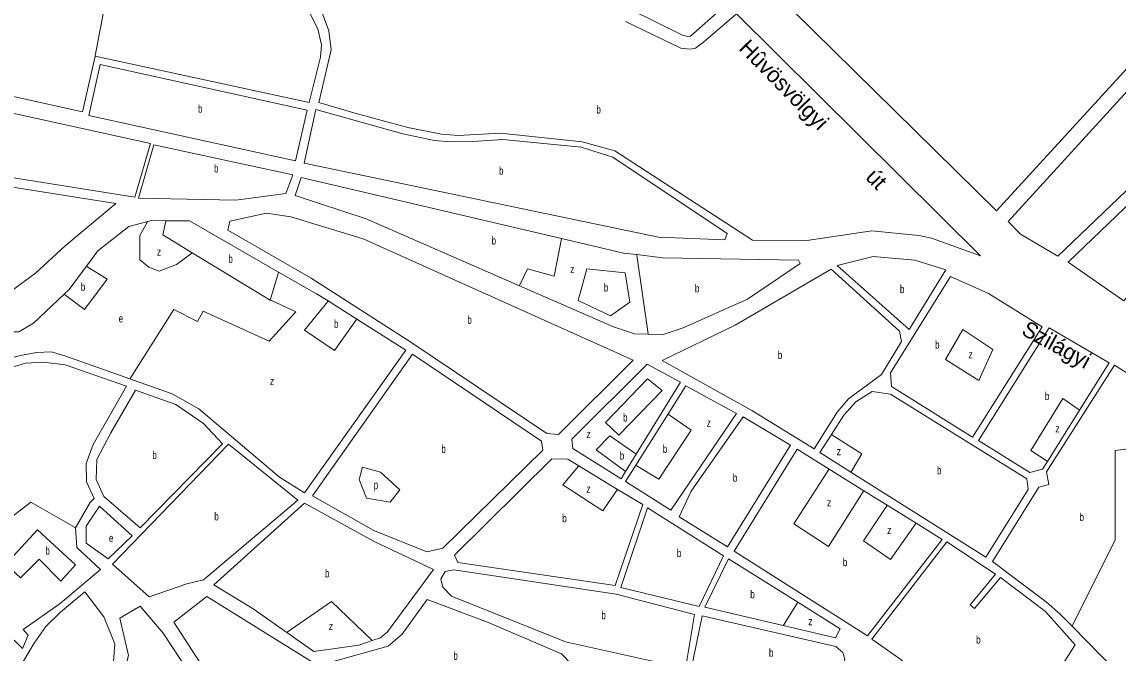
# Model space of a CAD drawing. Extents: x 639657 to 671642, y 222838 to 252123.
# Drawn here: x 644946 to 646316, y 241013 to 241801 of the extents above; entities that cross this region are included whole.
import ezdxf
from ezdxf.enums import TextEntityAlignment as Align

# ---------------------------------------------------------------- set-up
doc = ezdxf.new("R2010")
doc.units = 0
doc.header["$LTSCALE"] = 4
doc.layers.add('1', color=7, linetype='Continuous', lineweight=13)
doc.layers.add('21', color=7, linetype='Continuous', lineweight=13)
doc.layers.add('22', color=7, linetype='Continuous')
doc.layers.add('7', color=7, linetype='Continuous')

msp = doc.modelspace()

# ---------------------------------------------------------------- linework, layer by layer
at = {"layer": '1'}
for p, q in [((645294.9, 241607.15), (645620.206, 241530.732)), ((645004.92, 241467.24), (645026.293, 241496.041)), ((645942.86, 241263.31), (645957.318, 241285.861)), ((645828.86, 241130.7), (645915.416, 241076.328))]:
    msp.add_line(p, q, dxfattribs=at)
for points in [[(645858.47, 241865.89), (646093.56, 242109.01), (646187.78, 242031.94), (646214.33, 241999.51), (646251.88, 241958.28), (646371.69, 241821.18), (646376.66, 241813.26), (646376.91, 241804.46), (646374.59, 241796.51), (646367.97, 241788.32), (646163.68, 241565.33)], [(645623.52, 241961.51), (645494.3, 241854.3), (645497.53, 241851.96), (645507.65, 241846.42), (645520.12, 241842.82), (645705.57, 241817.4), (645771.43, 241784.83), (645777.88, 241782.92), (645781.32, 241783.58), (645824.74, 241821.75)], [(646178.34, 241551.87), (646402.29, 241797.05), (646433.14, 241765.19), (646467.24, 241725.61), (646240.37, 241508.54), (646193.44, 241536.26)], [(645106.26, 241649.4), (645086.89, 241582.34), (644817.41, 241625.16), (644745.05, 241620.53), (644683.4, 241628.38), (644656.74, 241641.65), (644628.6, 241649.55), (644601.96, 241651.44), (644539.47, 241650.27), (644554.95, 241770.56)], [(645043.37, 241748.13), (645302.41, 241691.25), (645287.45, 241627.66), (645029.27, 241684.33)], [(646253.29, 241501.08), (646475.02, 241714.05), (646508.76, 241660.31), (646322.64, 241452.84)], [(645298.63, 241624.7), (645313.15, 241691.73), (645421.73, 241661.48), (645461.29, 241653.27), (645480.84, 241651.63), (645509.4, 241651.75), (645546.54, 241654.48), (645644.51, 241644.79), (645684.07, 241632.5), (645826.88, 241536.92), (645824.12, 241529.18), (645741.43, 241532.5)], [(645110.79, 241647.97), (645284.17, 241610.39), (645275.74, 241586.8), (645213.24, 241578.58), (645091.3, 241581.24)], [(645709.56, 241378.97), (645616.36, 241286.02), (645601.55, 241287.34), (645431.58, 241401.34), (645307.04, 241481.09), (645203.27, 241541.25), (645205.66, 241552.62), (645251.2, 241562.38), (645281.68, 241558.01), (645372.21, 241530.52)], [(645964.48, 241497.07), (646009.38, 241508.12), (646061.76, 241503.69), (646100.37, 241491.58), (646054.67, 241416.97)], [(645956.96, 241492.36), (646042.43, 241414.86), (646044.76, 241402.18), (646019.75, 241361.02), (645978.89, 241330.42), (645964.46, 241313.93), (645935.58, 241268.05), (645857.76, 241315.91), (645745.63, 241378.45), (645837.2, 241422.67)], [(646106.15, 241483.19), (646153.55, 241462.25), (646220.64, 241420.43), (646133.57, 241282.81), (646032.6, 241345.75), (646031.35, 241362.93)], [(645433.88, 241386.28), (645595.03, 241277.47), (645596.72, 241266.3), (645471.7, 241144.04), (645451.94, 241139.59), (645385.67, 241166.16), (645308.72, 241209.5)], [(645775.61, 241346.82), (645838.64, 241312.31), (645756.76, 241191.42), (645700.17, 241227.2), (645712.987, 241247.523), (645753.099, 241311.125)], [(645196.23, 241274.37), (645093.58, 241169.2), (645048.13, 241208.53), (645038.6, 241229.75), (645039.57, 241254.87), (645057.05, 241288.22), (645087.54, 241341.37), (645138.07, 241323.32), (645172.51, 241299.83)], [(645847.01, 241308.21), (645906.39, 241272.63), (645827.5, 241145.73), (645767.04, 241183.02), (645781.94, 241214.97)], [(645290.576, 241203.955), (645203.75, 241273.97), (645058.97, 241124.19), (645104.65, 241083.36), (645151.82, 241099.43), (645172.55, 241104.39)], [(645042.543, 241196.564), (645083.53, 241159.5), (645053.37, 241130.61), (645025.92, 241150.06), (645026.24, 241171.35)], [(645727.49, 241194.49), (645822.43, 241134.58), (645792, 241071.11), (645694.18, 241094.97)], [(646101.68, 241151.7), (646162.34, 241111.62), (646130.68, 241073.05), (646136.26, 241068.53), (646168.77, 241107.31), (646224.92, 241064.66), (646261.96, 241023.13), (646180.92, 240897.73), (646142.33, 240922.31), (646093.48, 240961.5), (646044.21, 241004.78), (646007.77, 241030.42)], [(645786.4, 241061.25), (645775.07, 240993.66), (645624.89, 241026.88), (645482.71, 241083.91), (645471.57, 241095.1), (645469.24, 241105.62), (645474.84, 241114.84), (645485.58, 241116.75), (645688.15, 241086.61)], [(644991.7, 240939.28), (645008.1, 240899.42), (645042.03, 240953.01), (645059.49, 240991.08), (645061.72, 241024.37), (645048.06, 241058.24), (645024.33, 241089.28), (644993.95, 241063.95), (644975.56, 241045.99), (644961.2, 241025.13), (644946.85, 241001.48), (644975.69, 240965.66)], [(645308.72, 241001.71), (645177, 241083.64), (645135.47, 241051.49), (645185.8, 240973.75), (645205.97, 240922.94), (645226.87, 240903.49), (645242.77, 240900.76), (645270.69, 240952.4)], [(645251.66, 240876.75), (645141.82, 240854.42), (645034.32, 240838.33), (645015.47, 240881.41), (645067.96, 240967.28), (645078.95, 241010.05), (645068.25, 241056.38), (645093.53, 241071.73), (645122.43, 241037.7), (645168.22, 240968.31), (645187.94, 240921.37), (645205.64, 240896.96), (645231.24, 240884.18)], [(645664.14, 240929.33), (645644.75, 240986.48), (645619.91, 241012.08), (645527.7, 241051.38), (645452.21, 241079.69), (645420.98, 241036.62), (645403.34, 241021.43), (645329.01, 241000.79), (645369.31, 240976.43), (645396.12, 240967.78), (645423.59, 240965.78), (645486.28, 240969.7), (645599.81, 240959.33), (645626.2, 240952.82), (645648.93, 240941.17)], [(645795.62, 241059.51), (645962.97, 241021.31), (645971.75, 241013.56), (645974.09, 241005.18), (645971.27, 240995.32), (645948.85, 240957.38), (645782.15, 240992.57)]]:
    msp.add_lwpolyline(points, close=True, dxfattribs=at)
for points in [[(645037.09, 241758.62), (645304.73, 241700.49), (645318.86, 241757.43), (645320.08, 241772.88), (645315.48, 241792.61), (645306.16, 241811.25), (645292.56, 241826.86), (645270.59, 241840.72), (645127.41, 241918.46), (645135.72, 241933.95), (645116.95, 241950.82), (645084.37, 241996.49), (645078.639, 242000.453)], [(645700.06, 241801.71), (645769.14, 241768.72), (645780.32, 241767.26), (645787.4, 241768.58), (645797.46, 241776.13), (645838.53, 241811.5), (646143.74, 241509.01), (646082.44, 241531.09), (646066.75, 241534.67), (646007.89, 241540.45), (645926.77, 241528.1), (645858.91, 241528.9), (645686.83, 241640.24), (645645.98, 241651.67), (645543.71, 241662.41), (645490.89, 241659.4), (645470.05, 241661.25), (645428.14, 241669.45), (645360.41, 241687.63), (645316.76, 241700.54), (645332.13, 241766.28), (645329.45, 241790.09), (645320.53, 241814.09)], [(644576.8, 241787.77), (645021.54, 241689.2), (645037.09, 241758.62)], [(644708.734, 241612.95), (644744.64, 241608.5), (644835.91, 241610.37), (645062.99, 241574.55)], [(645567.455, 241471.564), (645375.92, 241555.2), (645287.33, 241584.41), (645294.9, 241607.15)], [(645062.99, 241574.55), (644999.49, 241521.29), (644962.82, 241487.3), (644908.55, 241448.13), (644832.57, 241416.86), (644705.42, 241424.17), (644533.43, 241398.98), (644486.42, 241386.24), (644467.47, 241417.35)], [(645026.293, 241496.041), (645040.51, 241515.2), (645079.44, 241545.8), (645102.976, 241551.985)], [(645102.976, 241551.985), (645107.79, 241553.25), (645125.865, 241553.04)], [(645125.865, 241553.04), (645155.23, 241552.7), (645266.6, 241488.903)], [(645620.206, 241530.732), (645697.65, 241512.54), (645714.032, 241510.624)], [(645714.032, 241510.624), (645746.37, 241506.84), (645916.19, 241503.63), (645918.12, 241499.54), (645852.52, 241455.05), (645772.14, 241419.18), (645747, 241410.87), (645728.363, 241411.361)], [(645266.6, 241488.903), (645314.07, 241461.71), (645328.331, 241452.72), (645364.287, 241430.052)], [(645080.793, 241355.346), (644999.28, 241384.27), (644982.52, 241389.4), (644963.84, 241388.51), (644943.87, 241384.61), (644914.24, 241377.26), (644901.36, 241377.24), (644887.39, 241384.09), (644876.63, 241396.53), (644910.96, 241414.2), (644942.1, 241414.25), (644960.13, 241425.02), (644998.619, 241461.301), (645004.92, 241467.24)], [(645728.363, 241411.361), (645711.36, 241411.81), (645684.97, 241420.25), (645567.455, 241471.564)], [(645364.287, 241430.052), (645425.52, 241391.45), (645298.85, 241213.17), (645267.56, 241232.78), (645166.67, 241317.83), (645133.65, 241336.59), (645080.793, 241355.346)], [(646227.269, 241252.227), (646221.28, 241242.66), (646205.38, 241238.62), (646141.07, 241278.49), (646229.44, 241419.33)], [(646229.44, 241419.33), (646304.48, 241375.56), (646267.492, 241316.477), (646227.269, 241252.227)], [(645012.85, 241169.32), (645030.98, 241200.95), (645036.11, 241206.12), (645026.58, 241226.91), (645026.07, 241249.67), (645034.78, 241273.32), (645076.36, 241346.26), (644999.73, 241373.11), (644972.88, 241376.29), (644950.11, 241374.96), (644922.64, 241366.54)], [(645700.112, 241239.636), (645694.59, 241230.65), (645634.14, 241268.37), (645633.1, 241279.97), (645726.94, 241373.77)], [(645726.94, 241373.77), (645768.75, 241351.34), (645713.404, 241261.268), (645700.112, 241239.636)], [(646258.097, 241046.403), (646243.37, 241061.39), (646226.23, 241076.68), (646158.73, 241127.3), (646216.5, 241220.34), (646228.96, 241223.31), (646226.21, 241239.42), (646310.91, 241372.76)], [(646310.91, 241372.76), (646361.51, 241341.07), (646456.485, 241240.94)], [(645957.318, 241285.861), (645972.82, 241310.04), (645987.68, 241326.75), (646008.11, 241339.58), (646031.29, 241336.31), (646201.71, 241230.68), (646203.39, 241217.15), (646150.37, 241132.91), (645981.524, 241239.014), (645942.86, 241263.31)], [(646063.12, 241175.164), (646095.68, 241154.94), (646002.63, 241034.51), (645835.86, 241140.34), (645914.53, 241267.46)], [(645914.53, 241267.46), (645954.501, 241242.632), (645997.793, 241215.742), (646027.097, 241197.54), (646063.12, 241175.164)], [(645690.119, 241217.352), (645721.48, 241198.37), (645687.31, 241097.14), (645490.33, 241125.97), (645486.49, 241135.42), (645607.86, 241255.54)], [(645607.86, 241255.54), (645627.82, 241255.06), (645641.523, 241246.766), (645690.119, 241217.352)], [(646456.485, 241240.94), (646531.75, 241161.59), (646404.34, 241038.24), (646398.72, 241021.51), (646410.23, 240990.35), (646389.8, 240976.87), (646373.86, 240954.37), (646336.33, 240973.35), (646311.47, 240992.09), (646258.097, 241046.403)], [(645276.805, 241038.585), (645234.73, 241068.22), (645185.43, 241097.97), (645298.82, 241200.29), (645386.07, 241152.2), (645460.04, 241117.24)], [(644993.68, 241074.72), (645043.76, 241117.48), (645014.45, 241144.85), (645012.85, 241169.32)], [(645897.041, 241047.441), (645799.09, 241070.45), (645828.86, 241130.7)], [(645460.04, 241117.24), (645402.53, 241039.46), (645393.92, 241032.18), (645383.641, 241028.649)], [(644876.758, 241081.749), (644904.23, 241059.4), (644946.611, 241018.583), (644953.45, 241035.21), (644947.22, 241042.29), (644993.68, 241074.72)], [(645915.416, 241076.328), (645968.17, 241043.19), (645962.56, 241032.05), (645897.041, 241047.441)], [(645383.641, 241028.649), (645366.64, 241022.81), (645310.59, 241014.79), (645276.805, 241038.585)]]:
    msp.add_lwpolyline(points, dxfattribs=at)
at = {"layer": '21'}
for points in [[(645053.824, 241945.481), (645033.777, 241900.353), (645060.507, 241881.967), (645037.185, 241759.12), (645037.09, 241758.62)], [(645158.643, 241513.001), (645158.143, 241512.626), (645138.804, 241498.114), (645117.475, 241489.986), (645104.272, 241495.066), (645093.1, 241504.211), (645093.1, 241534.694), (645102.69, 241551.485), (645102.976, 241551.985)], [(645158.643, 241513.001), (645122.043, 241535.193), (645125.758, 241552.54), (645125.865, 241553.04)], [(645567.455, 241471.564), (645567.69, 241472.064), (645577.554, 241493.034), (645611.07, 241483.889), (645620.108, 241530.232), (645620.206, 241530.732)], [(645266.6, 241488.903), (645266.45, 241488.403), (645256.105, 241453.905), (645158.643, 241513.001)], [(645728.363, 241411.361), (645728.291, 241411.862), (645714.104, 241510.123), (645714.032, 241510.624)], [(645026.293, 241496.041), (645026.792, 241495.731), (645052.475, 241479.824), (645024.038, 241442.229), (644999.119, 241460.926), (644998.619, 241461.301)], [(645256.105, 241453.905), (645256.605, 241453.675), (645288.101, 241439.18), (645254.585, 241402.601), (645172.319, 241440.197), (645165.21, 241426.987), (645135.757, 241442.229), (645081.109, 241355.846), (645080.793, 241355.346)], [(645364.287, 241430.052), (645363.93, 241429.552), (645336.339, 241390.906), (645298.761, 241416.309), (645327.925, 241452.22), (645328.331, 241452.72)], [(646267.492, 241316.477), (646266.992, 241316.819), (646246.339, 241330.957), (646206.729, 241265.926), (646226.769, 241252.56), (646227.269, 241252.227)], [(645712.987, 241247.523), (645713.487, 241247.223), (645741.573, 241230.363), (645782.198, 241291.329), (645753.599, 241310.785), (645753.099, 241311.125)], [(645713.404, 241261.268), (645712.904, 241261.618), (645680.636, 241284.216), (645663.37, 241266.942), (645699.612, 241240.008), (645700.112, 241239.636)], [(645957.318, 241285.861), (645957.818, 241285.547), (645995.48, 241261.862), (645981.829, 241239.514), (645981.524, 241239.014)], [(646456.485, 241240.94), (646455.985, 241241.132), (646371.581, 241273.47), (646311.793, 241265.994), (646311.793, 241153.842), (646258.347, 241046.903), (646258.097, 241046.403)], [(645641.523, 241246.766), (645641.102, 241246.266), (645621.73, 241223.25), (645671.495, 241190.735), (645689.769, 241216.852), (645690.119, 241217.352)], [(645954.501, 241242.632), (645954.176, 241242.132), (645910.167, 241174.477), (645953.839, 241146.027), (645997.478, 241215.242), (645997.793, 241215.742)], [(645012.85, 241169.32), (645012.35, 241169.607), (644957.006, 241201.414), (644905.209, 241161.786), (644836.146, 241200.398), (644819.896, 241180.076), (644804.662, 241183.124), (644785.365, 241183.124), (644778.256, 241172.963), (644783.334, 241144.512), (644811, 241108.07), (644811.38, 241107.57)], [(646027.097, 241197.54), (646026.764, 241197.04), (645997.511, 241153.139), (646031.026, 241129.769), (646062.767, 241174.664), (646063.12, 241175.164)], [(645383.641, 241028.649), (645383.141, 241029.129), (645332.788, 241077.449), (645277.305, 241038.932), (645276.805, 241038.585)], [(645915.416, 241076.328), (645915.098, 241075.828), (645897.359, 241047.941), (645897.041, 241047.441)]]:
    msp.add_lwpolyline(points, dxfattribs=at)
for points in [[(645640.837, 241453.204), (645681.148, 241434.1), (645705.523, 241451.374), (645699.429, 241487.954), (645651.695, 241493.034)], [(646121.499, 241416.932), (646100.089, 241379.729), (646141.729, 241353.311), (646158.995, 241391.923)], [(645674.881, 241300.864), (645727.355, 241355.343), (645745.636, 241341.118), (645691.808, 241285.232)], [(645376.47, 241206.323), (645367.319, 241229.864), (645371.382, 241245.106), (645393.726, 241239.009), (645418.101, 241216.655), (645405.913, 241201.413)], [(644994.487, 241102.948), (645012.865, 241123.174), (644965.131, 241166.866), (644925.521, 241124.19), (644943.803, 241106.916), (644967.162, 241130.287)]]:
    msp.add_lwpolyline(points, close=True, dxfattribs=at)

# ---------------------------------------------------------------- texts
at = {"layer": '22'}
for s, rotation, p in [('Hûvösvölgyi           út', 314.49, (645927.476, 241678.778)), ('Szilágyi', 331.367, (646233.963, 241389.366))]:
    msp.add_text(s, height=20, rotation=rotation, dxfattribs=at).set_placement(p, align=Align.CENTER)
at = {"layer": '7'}
for s, width, p in [('b', 0.75, (645165.839, 241687.895)), ('b', 0.75, (645663.666, 241686.91)), ('b', 0.75, (645185.758, 241613.275)), ('b', 0.75, (645542.026, 241610.455)), ('b', 0.75, (645532.651, 241523.235)), ('z', 0.8, (645114.428, 241509.292)), ('b', 0.75, (645203.707, 241500.431)), ('z', 0.8, (645630.864, 241487.66)), ('b', 0.75, (645019.329, 241465.514)), ('b', 0.75, (645672.992, 241464.542)), ('b', 0.75, (645786.742, 241463.526)), ('b', 0.75, (646042.97, 241462.545)), ('e', 0.75, (645066.684, 241425.921)), ('b', 0.75, (645335.738, 241419.143)), ('b', 0.75, (645502.38, 241424.2)), ('b', 0.75, (646086.88, 241393.161)), ('b', 0.75, (645890.336, 241380.205)), ('z', 0.8, (646128.521, 241380.968)), ('z', 0.8, (645255.6, 241347.732)), ('b', 0.75, (646224.031, 241328.975)), ('b', 0.75, (645696.955, 241302.21)), ('z', 0.8, (645801.489, 241295.617)), ('z', 0.8, (645651.177, 241281.391)), ('z', 0.8, (646237.192, 241288.503)), ('b', 0.75, (645108.695, 241255.285)), ('b', 0.75, (645469.915, 241262.935)), ('b', 0.75, (645692.893, 241254.453)), ('b', 0.75, (645746.669, 241263.023)), ('z', 0.8, (645963.989, 241260.053)), ('b', 0.75, (645834.16, 241226.97)), ('b', 0.75, (646089.331, 241236.245)), ('p', 0.75, (645385.315, 241218)), ('z', 0.8, (645651.177, 241213.313)), ('z', 0.8, (645951.802, 241196.039)), ('b', 0.75, (645186.112, 241178.665)), ('b', 0.75, (645620.94, 241176.34)), ('b', 0.75, (646267.378, 241177.944)), ('z', 0.8, (646026.958, 241161.491)), ('e', 0.75, (645054.496, 241151.573)), ('b', 0.75, (644975.077, 241135.99)), ('b', 0.75, (645764.209, 241132.8)), ('b', 0.75, (645971.598, 241121.518)), ('b', 0.75, (645324.452, 241107.54)), ('b', 0.75, (645855.935, 241081.375)), ('b', 0.75, (645669.83, 241055.205)), ('z', 0.8, (645329.223, 241041.592)), ('z', 0.8, (645928.442, 241047.688)), ('b', 0.75, (646138.212, 241024.715)), ('b', 0.75, (645879.261, 241008.445)), ('b', 0.75, (645484.831, 241004.51))]:
    msp.add_text(s, height=10, dxfattribs=dict(at, width=width)).set_placement(p)

doc.saveas('drawing.dxf')
